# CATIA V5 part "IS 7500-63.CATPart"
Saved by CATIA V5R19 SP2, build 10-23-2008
Part number: IS 7500-63
Bounding box of the stored display mesh (mm): x -74.81 to 74.81, y -74.81 to 74.81, z 0 to 282
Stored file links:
  C:\Users\Bora\Desktop\3D Katı model\IS serisi\IS 7500\IS 7500-63.CATPart
  C:\Program Files\Dassault Systemes\B19\intel_a\reffiles\standard\MetricThickPitch.txt
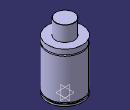
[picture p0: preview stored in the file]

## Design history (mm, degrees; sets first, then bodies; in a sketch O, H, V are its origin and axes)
Body1 (main body)
  Sketch1 on yz-plane, origin (0, 0, 0), H (0, 1, 0), V (0, 0, 1)
    point P1 (75, 194)
    point P4 (75, 189)
    point P7 (40, 281)
    point P9 (40, 281)
    point P13 (75, 194)
    point P14 (75, 189)
    line L1 (75, 194) -> (75, 216)
    line L2 (75, 15) -> (75, 189)
    line L3 (71, 15) -> (71, 8)
    arc A1 centre (39, 281) radius 1 from (40, 281) to (39, 282) ccw
    line L4 (40, 281) -> (40, 216)
    line L5 (75, 0) -> (75, 8)
    arc A2 centre (75, 191.5) radius 2.5 from (75, 194) to (75, 189) ccw
    line L6 (39, 282) -> (0, 282)
    point P15 (0, 282)
    line L7 (40, 216) -> (75, 216)
    line L8 (0, 0) -> (75, 0)
    line L9 (71, 15) -> (75, 15)
    line L10 (71, 8) -> (75, 8)
    coincidence: P15 V, P1 P13, P4 P14, P7 P9
    tangency: L6 A1
    horizontal: L7 H, L8 H, L9 H, L10 H
  Shaft1: profile Sketch1, axis Sketch1.V, angle 360
  Sketch2 on face of Shaft1 from Sketch1.L8, origin (0, 0, 0), H (1, 0, 0), V (0, -1, 0)
    point P1 (50, 0)
    distance P1 V = 50
  Hole1: placed by Sketch2, at (50, 0, 0) direction (0, 0, 1), diameter 8.376, depth 16, threaded "M10", thread diameter 10, thread depth 16, pitch 1.5
  CircPattern1: of Hole1, instances 4, angular step 90, axis from xy-plane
